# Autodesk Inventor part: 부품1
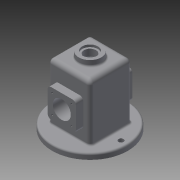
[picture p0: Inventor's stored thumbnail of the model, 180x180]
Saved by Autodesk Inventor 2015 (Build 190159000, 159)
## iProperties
Created: 2021-08
Part Number: 부품1
Material: 일반
Document SubType Name: Modeling
Designer: 104658
Density: 1 g/cm^3
Appearance: 기본값
Author: 104658
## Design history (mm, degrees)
sketch "스케치1"
  geometry: C1 r 67 at (0, 0); 1 further point
  constraints: 1 centre point, 1 coincident
  dimensions: "d0" = 134 diameter of C1
extrude "돌출1" new body sketch "스케치1" distance "d1" = 10; taper "d2" = 0 deg
sketch "스케치3"
  geometry: L1 (-37, -37)-(37, -37); L2 (37, -37)-(37, 37); L3 (37, 37)-(-37, 37); L4 (-37, 37)-(-37, -37); L5 (-37, -37)-(37, 37); L6 (37, -37)-(-37, 37); C1 r 67 at (0, 0) reference
  constraints: 12 end point, 2 midpoint, 2 parallel, 1 horizontal, 1 perpendicular
  dimensions: "d3" = 74 distance of L2.end L3.end; "d4" = 74 distance of L1.end L2.end
extrude "돌출2" join sketch "스케치3" distance "d5" = 100; taper "d6" = 0 deg
sketch "스케치6"
  geometry: 1 further point
sketch "스케치7"
  geometry: L1 (32, -32)-(-32, -32); L2 (-32, -32)-(-32, 32); L3 (-32, 32)-(32, 32); L4 (32, 32)-(32, -32); L5 (32, -32)-(-32, 32); L6 (-32, -32)-(32, 32); C1 r 67 at (0, 0) reference
  constraints: 12 end point, 2 midpoint, 2 parallel, 1 horizontal, 1 perpendicular
  dimensions: "d15" = 64 distance of L2.end L3.end; "d16" = 64 distance of L1.end L2.end
extrude "돌출5" cut sketch "스케치7" distance "d17" = 105; taper "d18" = 0 deg
sketch "스케치9"
  geometry: L1 (12, 70)-(62, 70); L2 (62, 70)-(62, 20); L3 (62, 20)-(12, 20); L4 (12, 20)-(12, 70); L5 (12, 70)-(62, 20); L6 (62, 70)-(12, 20); L7 (-30, -10)-(104, -10) reference; 4 further points
  constraints: 12 end point, 4 midpoint, 2 parallel, 1 horizontal, 1 perpendicular, 1 vertical alignment
  dimensions: "d24" = 55 distance from line of point (37, 45) L7; "d25" = 50 distance of L1.end L2.end; "d26" = 50 distance between parallel lines of L4 L2
extrude "돌출7" join sketch "스케치9" distance "d27" = 13; taper "d28" = 0 deg
sketch "스케치10"
  geometry: L1 (0, 0)-(64, 0) reference; L2 (0, 0)-(0, -105) reference; L3 (0, -105)-(64, -105) reference; L4 (64, 0)-(64, -105) reference; 1 further point
sketch "스케치11"
  geometry: L1 (0, 0)-(64, 0) reference; C1 r 25 at (32, -55); 2 further points
  constraints: 1 centre point, 1 midpoint, 1 vertical alignment
  dimensions: "d29" = 55 distance from line of C1.centre L1; "d30" = 50 diameter of C1
extrude "돌출8" join sketch "스케치11" distance "d31" = 7; taper "d32" = 0 deg
sketch "스케치12"
  geometry: L1 (-25, 30)-(-25, 80) reference; L2 (32, 0)-(-32, 0) reference; L3 (32, 0)-(32, 105) reference; L4 (32, 105)-(-32, 105) reference; L5 (-32, 0)-(-32, 105) reference; L6 (-32, 80)-(-25, 80) reference; L7 (-32, 30)-(-25, 30) reference; L8 (-50, 80)-(-50, 30) reference; L9 (-37, 80)-(-50, 80) reference; L10 (-50, 55)-(-25, 55); L11 (-32, 30)-(-25, 32.548); L12 (-25, 30)-(-32, 30); L13 (-32, 0)-(-32, 105) reference; L14 (-25, 32.548)-(-25, 30); 1 further point
  constraints: 8 end point, 2 midpoint, 1 collinear, 1 perpendicular, 1 point on line
  dimensions: "d33" = 110 deg angle of L11 L5
revolve "회전1" sketch "스케치12" stored, may be unused: angle "d34" = 90 deg
fillet "모깎기1" dims "d35" = 3
sketch "스케치13"
  geometry: L1 (-30, -10)-(104, -10) reference; 3 further points
  constraints: 1 midpoint, 1 vertical alignment
  dimensions: "d36" = 55 distance from line of point (37, 45) L1
hole "구멍1" sketch "스케치13" at (37, 45) diameter "d37" = 32; stored, may be unused: countersink angle "d41" = 90 deg, drill point angle "d43" = 118 deg; dims "d38" = 6, "d39" = 4, "d40" = 2, "d42" = 8
fillet "모깎기2" dims "d44" = 6
fillet "모깎기3" dims "d45" = 6
fillet "모깎기4" dims "d46" = 6
fillet "모깎기5" dims "d47" = 8
sketch "스케치14"
  geometry: 1 further point
hole "구멍2" sketch "스케치14" at (-55, 0) diameter "d49" = 9; stored, may be unused: countersink angle "d53" = 90 deg, drill point angle "d55" = 118 deg; dims "d50" = 6, "d51" = 4, "d52" = 2, "d54" = 8
sketch "스케치15"
  geometry: C1 r 16 at (37, 45) reference; 2 further points
  dimensions: "d56" = 17 horizontal distance of point (54, 62) C1.centre; "d57" = 17 horizontal distance of point (54, 62) C1.centre
hole "구멍3" sketch "스케치15" at (54, 62) diameter "d58" = 3.242; stored, may be unused: countersink angle "d62" = 90 deg, drill point angle "d64" = 118 deg; dims "d59" = 8, "d60" = 4, "d61" = 2, "d63" = 10
sketch "스케치18"
  geometry: L1 (19.488, -110)-(42.512, -110) reference; 2 further points
  constraints: 1 other
  dimensions: "d74" = 28 distance from line of point (31.154, -82) L1
feature "엠보싱1" sketch "스케치18" dims "d75" = 0.5, "d76" = 0
sketch "스케치20"
  geometry: C1 r 20 at (0, 0); 1 further point
  constraints: 1 centre point, 1 coincident
  dimensions: "d77" = 40 diameter of C1
extrude "돌출10" join sketch "스케치20" distance "d78" = 10; taper "d79" = 0 deg
sketch "스케치21"
  geometry: C1 r 20 at (0, 0) reference; 1 further point
  constraints: 1 coincident
hole "구멍4" sketch "스케치21" at (0, 0) diameter "d80" = 21; stored, may be unused: countersink angle "d84" = 90 deg, drill point angle "d86" = 118 deg; dims "d81" = 21, "d82" = 28, "d83" = 4, "d85" = 24.8
fillet "모깎기7" dims "d87" = 3
fillet "모깎기8" dims "d88" = 3
sketch "스케치22"
  geometry: 1 further point
node "솔리드1"
mirror "대칭1"
mirror "대칭2"
pattern_circular "원형 패턴1" dims angle "d66" = 360 deg
mirror "대칭3"
mirror "대칭4"
mirror "대칭5"
node "투영된 루프3"
